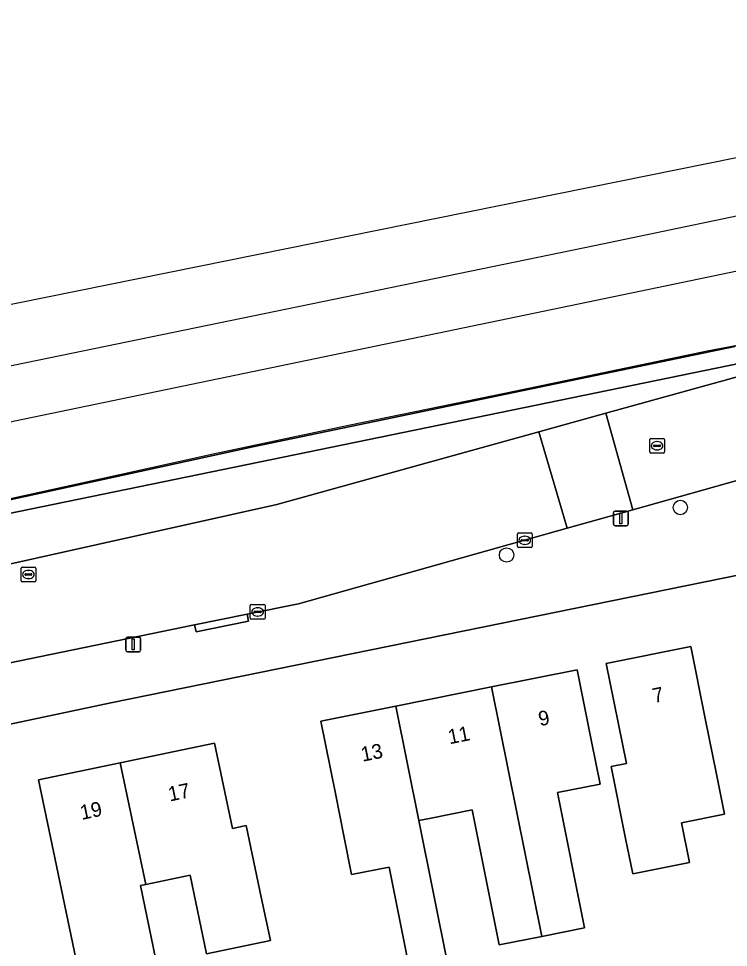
# Model space of a CAD drawing. Extents: x 162989 to 165008, y 383432 to 384338.
# Drawn here: x 164175.4 to 164223.8, y 384168.5 to 384231.8 of the extents above; entities that cross this region are included whole.
import ezdxf

# ---------------------------------------------------------------- set-up
doc = ezdxf.new("R2010")
doc.units = 0
for name, color, linetype in [('IMGEO_Boom', 7, 'Continuous'), ('IMGEO_Erf', 7, 'Continuous'), ('IMGEO_Geluidsscherm', 7, 'Continuous'), ('IMGEO_Groenvoorziening', 7, 'Continuous'), ('IMGEO_Haag', 7, 'Continuous'), ('IMGEO_Kolk', 7, 'Continuous'), ('IMGEO_Lichtmast', 7, 'Continuous'), ('IMGEO_Pand', 7, 'Continuous'), ('IMGEO_Pand_nummerreeks', 7, 'Continuous'), ('IMGEO_Rijbaan_lokaal_gesloten', 7, 'Continuous'), ('IMGEO_Rijbaan_lokaal_open', 7, 'Continuous'), ('IMGEO_Rioolput', 7, 'Continuous'), ('IMGEO_Spoor', 7, 'Continuous'), ('IMGEO_Spoorbaan_halfverhard', 7, 'Continuous'), ('IMGEO_Voetpad_open', 7, 'Continuous')]:
    doc.layers.add(name, color=color, linetype=linetype)

msp = doc.modelspace()

# ---------------------------------------------------------------- linework, layer by layer
at = {"layer": 'IMGEO_Boom'}
for centre in [(164220.485, 384198.529), (164208.651, 384195.29)]:
    msp.add_circle(centre, 0.489, dxfattribs=at)
at = {"layer": 'IMGEO_Erf'}
for points in [[(164247.023, 384197.746), (164245.464, 384197.793), (164245.375, 384198.004), (164230.991, 384195.25), (164181.684, 384185.212), (164136.425, 384175.642), (164077.591, 384163.416), (164035.172, 384154.601)], [(164203.02, 384162.177), (164200.646, 384174.026), (164198.091, 384173.514), (164197.585, 384176.041), (164196.985, 384179.036), (164195.995, 384183.977), (164201.106, 384185.001), (164207.622, 384186.306), (164213.46, 384187.476), (164214.443, 384182.574), (164215.022, 384179.683), (164212.112, 384179.1), (164213.959, 384169.885), (164211.04, 384169.3), (164208.139, 384168.719), (164206.296, 384177.918), (164203.395, 384177.336), (164202.674, 384177.191), (164206.648, 384157.404)]]:
    msp.add_lwpolyline(points, dxfattribs=at)
for points in [[(164215.445, 384187.894), (164221.202, 384189.047), (164222.185, 384184.145), (164222.943, 384180.361), (164223.49, 384177.628), (164220.574, 384177.044), (164221.115, 384174.346), (164217.241, 384173.57), (164216.759, 384175.974), (164215.777, 384180.876), (164216.81, 384181.083)], [(164177.779, 384175.085), (164176.758, 384179.971), (164182.328, 384181.135), (164188.753, 384182.478), (164189.969, 384176.66), (164190.919, 384176.858), (164191.942, 384171.964), (164192.557, 384169.024), (164188.208, 384168.115), (164187.089, 384173.468), (164184.065, 384172.836), (164183.705, 384172.761), (164185.174, 384165.726), (164182.634, 384165.195), (164179.963, 384164.637)]]:
    msp.add_lwpolyline(points, close=True, dxfattribs=at)
at = {"layer": 'IMGEO_Geluidsscherm'}
msp.add_lwpolyline([(164171.413, 384198.388), (164182.191, 384200.754), (164188.653, 384202.187), (164197.889, 384204.143), (164208.612, 384206.353), (164222.309, 384209.203), (164232.177, 384211.07), (164237.019, 384211.987)], dxfattribs=at)
at = {"layer": 'IMGEO_Groenvoorziening'}
for points in [[(163892.745, 384139.603), (163976.433, 384156.982), (164073.867, 384177.406), (164173.737, 384197.907), (164238.498, 384211.23), (164245.279, 384212.748), (164245.015, 384213.611), (164238.302, 384212.109), (164224.204, 384209.495), (164191.357, 384202.662), (164184.194, 384201.103), (164173.545, 384198.786), (164138.86, 384191.809), (164106.067, 384184.851), (164073.689, 384178.288), (164040.716, 384171.257), (164027.429, 384168.427), (164008.211, 384164.605), (163976.248, 384157.863), (163965.539, 384155.519), (163953.785, 384153.248), (163943.293, 384151.084)], [(164013.045, 384161.087), (164068.214, 384172.427), (164075.211, 384173.907), (164100.528, 384179.263), (164113.878, 384181.981), (164118.515, 384182.925), (164132.64, 384185.801), (164174.669, 384194.637), (164193.008, 384198.736), (164210.847, 384203.689), (164215.404, 384204.954), (164225.51, 384207.76), (164243.827, 384211.591), (164248.158, 384212.497), (164247.376, 384214.139), (164245.015, 384213.611), (164245.279, 384212.748), (164238.498, 384211.23), (164173.737, 384197.907), (164073.867, 384177.406), (163976.433, 384156.982)]]:
    msp.add_lwpolyline(points, dxfattribs=at)
at = {"layer": 'IMGEO_Haag'}
msp.add_lwpolyline([(163892.745, 384139.603), (163976.433, 384156.982), (164073.867, 384177.406), (164173.737, 384197.907), (164238.498, 384211.23), (164245.279, 384212.748), (164245.015, 384213.611), (164238.302, 384212.109), (164224.204, 384209.495), (164191.357, 384202.662), (164184.194, 384201.103), (164173.545, 384198.786), (164138.86, 384191.809), (164106.067, 384184.851), (164073.689, 384178.288), (164040.716, 384171.257), (164027.429, 384168.427), (164008.211, 384164.605), (163976.248, 384157.863), (163965.539, 384155.519), (163953.785, 384153.248), (163943.293, 384151.084)], dxfattribs=at)
at = {"layer": 'IMGEO_Kolk'}
for p, q in [((164209.388, 384195.868), (164209.388, 384196.72)), ((164209.463, 384196.794), (164210.315, 384196.794)), ((164209.876, 384196.574), (164209.901, 384196.574)), ((164210.389, 384196.72), (164210.389, 384195.868)), ((164209.647, 384196.288), (164209.647, 384196.3)), ((164210.085, 384196.251), (164209.687, 384196.251)), ((164209.69, 384196.337), (164210.088, 384196.337)), ((164209.899, 384196.014), (164209.874, 384196.014)), ((164210.131, 384196.3), (164210.131, 384196.288)), ((164210.315, 384195.794), (164209.463, 384195.794)), ((164191.192, 384190.988), (164191.192, 384191.84)), ((164191.267, 384191.914), (164192.119, 384191.914)), ((164191.451, 384191.408), (164191.451, 384191.42)), ((164191.494, 384191.457), (164191.892, 384191.457)), ((164191.68, 384191.694), (164191.705, 384191.694)), ((164191.935, 384191.42), (164191.935, 384191.408)), ((164192.193, 384191.84), (164192.193, 384190.988)), ((164192.119, 384190.914), (164191.267, 384190.914)), ((164191.889, 384191.371), (164191.491, 384191.371)), ((164191.703, 384191.134), (164191.678, 384191.134))]:
    msp.add_line(p, q, dxfattribs=at)
for points in [[(164209.388, 384195.868), (164209.388, 384196.72)], [(164209.463, 384196.794), (164210.315, 384196.794)], [(164210.389, 384196.72), (164210.389, 384195.868)], [(164210.315, 384195.794), (164209.463, 384195.794)], [(164191.192, 384190.988), (164191.192, 384191.84)], [(164191.267, 384191.914), (164192.119, 384191.914)], [(164192.193, 384191.84), (164192.193, 384190.988)], [(164192.119, 384190.914), (164191.267, 384190.914)]]:
    msp.add_lwpolyline(points, dxfattribs=at)
for centre, radius, start, end in [((164209.465, 384196.718), 0.0765, 91.55205, 178.44795), ((164209.465, 384196.718), 0.0765, 91.55205, 178.44795), ((164210.313, 384196.718), 0.0765, 1.55205, 88.44795), ((164210.313, 384196.718), 0.0765, 1.55205, 88.44795), ((164209.465, 384195.87), 0.0765, 181.55205, 268.44795), ((164209.465, 384195.87), 0.0765, 181.55205, 268.44795), ((164209.687, 384196.297), 0.0403, 85.87752, 175.75265), ((164209.684, 384196.287), 0.0366, 178.93798, 274.71019), ((164210.088, 384196.294), 0.043, 264.86636, 352.45326), ((164210.092, 384196.299), 0.0386, 1.73085, 96.63898), ((164210.313, 384195.87), 0.0765, 271.55205, 358.44795), ((164210.313, 384195.87), 0.0765, 271.55205, 358.44795), ((164191.269, 384191.838), 0.0765, 91.55205, 178.44795), ((164191.269, 384191.838), 0.0765, 91.55205, 178.44795), ((164191.491, 384191.417), 0.0403, 85.87752, 175.75265), ((164191.488, 384191.407), 0.0366, 178.93798, 274.71019), ((164191.892, 384191.414), 0.043, 264.86636, 352.45326), ((164191.896, 384191.419), 0.0386, 1.73085, 96.63898), ((164192.117, 384191.838), 0.0765, 1.55205, 88.44795), ((164192.117, 384191.838), 0.0765, 1.55205, 88.44795), ((164191.269, 384190.99), 0.0765, 181.55205, 268.44795), ((164191.269, 384190.99), 0.0765, 181.55205, 268.44795), ((164192.117, 384190.99), 0.0765, 271.55205, 358.44795), ((164192.117, 384190.99), 0.0765, 271.55205, 358.44795)]:
    msp.add_arc(centre, radius, start, end, dxfattribs=at)
for centre, major_axis, ratio, start_param, end_param in [((164209.875, 384196.294), (-0.387, 0.002), 0.722429, 4.712389, 7.853982), ((164209.9, 384196.294), (-0.39, 0.002), 0.717154, 1.570796, 4.712389), ((164191.679, 384191.414), (-0.387, 0.002), 0.722429, 4.712389, 7.853982), ((164191.704, 384191.414), (-0.39, 0.002), 0.717154, 1.570796, 4.712389)]:
    msp.add_ellipse(centre, major_axis=major_axis, ratio=ratio, start_param=start_param, end_param=end_param, dxfattribs=at)
at = {"layer": 'IMGEO_Lichtmast'}
for p, q in [((164215.938, 384197.387), (164215.938, 384198.187)), ((164215.938, 384198.187), (164215.938, 384197.387)), ((164216.038, 384198.287), (164216.828, 384198.287)), ((164216.828, 384198.287), (164216.038, 384198.287)), ((164216.928, 384198.187), (164216.928, 384197.387)), ((164216.928, 384197.387), (164216.928, 384198.187)), ((164216.828, 384197.287), (164216.038, 384197.287)), ((164216.038, 384197.287), (164216.828, 384197.287)), ((164182.72, 384188.798), (164182.72, 384189.598)), ((164182.72, 384189.598), (164182.72, 384188.798)), ((164182.82, 384189.698), (164183.61, 384189.698)), ((164183.61, 384189.698), (164182.82, 384189.698)), ((164183.71, 384189.598), (164183.71, 384188.798)), ((164183.71, 384188.798), (164183.71, 384189.598)), ((164183.61, 384188.698), (164182.82, 384188.698)), ((164182.82, 384188.698), (164183.61, 384188.698))]:
    msp.add_line(p, q, dxfattribs=at)
for points in [[(164216.358, 384198.162), (164216.508, 384198.162), (164216.508, 384197.412), (164216.358, 384197.412), (164216.358, 384198.162)], [(164183.14, 384189.573), (164183.29, 384189.573), (164183.29, 384188.823), (164183.14, 384188.823), (164183.14, 384189.573)]]:
    msp.add_lwpolyline(points, dxfattribs=at)
for centre, start, end in [((164216.038, 384198.187), 90, 180), ((164216.038, 384198.187), 90, 180), ((164216.828, 384198.187), 0, 90), ((164216.828, 384198.187), 360, 90), ((164216.038, 384197.387), 180, 270), ((164216.038, 384197.387), 180, 270), ((164216.828, 384197.387), 270, 0), ((164216.828, 384197.387), 270, 0), ((164182.82, 384189.598), 90, 180), ((164182.82, 384189.598), 90, 180), ((164183.61, 384189.598), 0, 90), ((164183.61, 384189.598), 360, 90), ((164182.82, 384188.798), 180, 270), ((164182.82, 384188.798), 180, 270), ((164183.61, 384188.798), 270, 0), ((164183.61, 384188.798), 270, 0)]:
    msp.add_arc(centre, 0.1, start, end, dxfattribs=at)
at = {"layer": 'IMGEO_Pand'}
for points in [[(164222.185, 384184.145), (164221.202, 384189.047), (164215.445, 384187.894), (164216.81, 384181.083), (164215.777, 384180.876), (164216.759, 384175.974), (164217.241, 384173.57), (164221.115, 384174.346), (164220.574, 384177.044), (164223.49, 384177.628), (164222.943, 384180.361)], [(164207.622, 384186.306), (164211.04, 384169.3), (164213.959, 384169.885), (164212.112, 384179.1), (164215.022, 384179.683), (164214.443, 384182.574), (164213.46, 384187.476)], [(164207.622, 384186.306), (164201.106, 384185.001), (164202.674, 384177.191), (164203.395, 384177.336), (164206.296, 384177.918), (164208.139, 384168.719), (164211.04, 384169.3)], [(164201.106, 384185.001), (164195.995, 384183.977), (164196.985, 384179.036), (164197.585, 384176.041), (164198.091, 384173.514), (164200.646, 384174.026), (164203.02, 384162.177), (164202.452, 384162.075), (164203.429, 384156.8), (164203.437, 384156.759), (164206.648, 384157.404), (164202.674, 384177.191)], [(164184.065, 384172.836), (164187.089, 384173.468), (164188.208, 384168.115), (164192.557, 384169.024), (164191.942, 384171.964), (164190.919, 384176.858), (164189.969, 384176.66), (164188.753, 384182.478), (164182.328, 384181.135)], [(164184.065, 384172.836), (164182.328, 384181.135), (164176.758, 384179.971), (164177.779, 384175.085), (164179.963, 384164.637), (164182.634, 384165.195), (164185.174, 384165.726), (164183.705, 384172.761)]]:
    msp.add_lwpolyline(points, close=True, dxfattribs=at)
at = {"layer": 'IMGEO_Rijbaan_lokaal_gesloten'}
msp.add_lwpolyline([(164248.757, 384212.622), (164248.158, 384212.497), (164243.827, 384211.591), (164225.51, 384207.76), (164215.404, 384204.954), (164217.248, 384198.372), (164226.93, 384201.094), (164244.619, 384204.64), (164249.169, 384205.552), (164261.438, 384207.238)], dxfattribs=at)
msp.add_lwpolyline([(164151.108, 384182.957), (164157.853, 384184.381), (164170.754, 384187.105), (164173.805, 384187.749), (164187.396, 384190.533), (164190.968, 384191.257), (164194.467, 384191.967), (164212.777, 384197.115), (164210.847, 384203.689), (164193.008, 384198.736), (164174.669, 384194.637), (164132.64, 384185.801), (164118.515, 384182.925), (164119.87, 384176.388), (164129.874, 384178.473), (164133.253, 384179.185), (164134.588, 384179.467), (164137.721, 384180.13)], close=True, dxfattribs=at)
at = {"layer": 'IMGEO_Rijbaan_lokaal_open'}
msp.add_lwpolyline([(164210.847, 384203.689), (164212.777, 384197.115), (164217.248, 384198.372), (164215.404, 384204.954)], close=True, dxfattribs=at)
at = {"layer": 'IMGEO_Rioolput'}
for p, q in [((164218.403, 384202.312), (164218.403, 384203.164)), ((164218.478, 384203.238), (164219.33, 384203.238)), ((164218.891, 384203.018), (164218.916, 384203.018)), ((164219.404, 384203.164), (164219.404, 384202.312)), ((164219.33, 384202.238), (164218.478, 384202.238)), ((164218.662, 384202.732), (164218.662, 384202.744)), ((164219.1, 384202.695), (164218.702, 384202.695)), ((164218.705, 384202.781), (164219.103, 384202.781)), ((164218.914, 384202.458), (164218.889, 384202.458)), ((164219.146, 384202.744), (164219.146, 384202.732)), ((164175.573, 384193.541), (164175.573, 384194.393)), ((164175.648, 384194.467), (164176.5, 384194.467)), ((164175.832, 384193.961), (164175.832, 384193.973)), ((164175.875, 384194.01), (164176.273, 384194.01)), ((164176.061, 384194.247), (164176.086, 384194.247)), ((164176.316, 384193.973), (164176.316, 384193.961)), ((164176.574, 384194.393), (164176.574, 384193.541)), ((164176.5, 384193.467), (164175.648, 384193.467)), ((164176.27, 384193.924), (164175.872, 384193.924)), ((164176.084, 384193.687), (164176.059, 384193.687))]:
    msp.add_line(p, q, dxfattribs=at)
for points in [[(164218.403, 384202.312), (164218.403, 384203.164)], [(164218.478, 384203.238), (164219.33, 384203.238)], [(164219.404, 384203.164), (164219.404, 384202.312)], [(164219.33, 384202.238), (164218.478, 384202.238)], [(164175.573, 384193.541), (164175.573, 384194.393)], [(164175.648, 384194.467), (164176.5, 384194.467)], [(164176.574, 384194.393), (164176.574, 384193.541)], [(164176.5, 384193.467), (164175.648, 384193.467)]]:
    msp.add_lwpolyline(points, dxfattribs=at)
for centre, radius, start, end in [((164218.48, 384203.162), 0.0765, 91.55205, 178.44795), ((164218.48, 384203.162), 0.0765, 91.55205, 178.44795), ((164219.328, 384203.162), 0.0765, 1.55205, 88.44795), ((164219.328, 384203.162), 0.0765, 1.55205, 88.44795), ((164218.48, 384202.314), 0.0765, 181.55205, 268.44795), ((164218.48, 384202.314), 0.0765, 181.55205, 268.44795), ((164218.702, 384202.741), 0.0403, 85.87752, 175.75265), ((164218.699, 384202.731), 0.0366, 178.93798, 274.71019), ((164219.103, 384202.738), 0.043, 264.86636, 352.45326), ((164219.107, 384202.743), 0.0386, 1.73085, 96.63898), ((164219.328, 384202.314), 0.0765, 271.55205, 358.44795), ((164219.328, 384202.314), 0.0765, 271.55205, 358.44795), ((164175.65, 384194.391), 0.0765, 91.55205, 178.44795), ((164175.65, 384194.391), 0.0765, 91.55205, 178.44795), ((164175.872, 384193.97), 0.0403, 85.87752, 175.75265), ((164175.869, 384193.96), 0.0366, 178.93798, 274.71019), ((164176.273, 384193.967), 0.043, 264.86636, 352.45326), ((164176.277, 384193.972), 0.0386, 1.73085, 96.63898), ((164176.498, 384194.391), 0.0765, 1.55205, 88.44795), ((164176.498, 384194.391), 0.0765, 1.55205, 88.44795), ((164175.65, 384193.543), 0.0765, 181.55205, 268.44795), ((164175.65, 384193.543), 0.0765, 181.55205, 268.44795), ((164176.498, 384193.543), 0.0765, 271.55205, 358.44795), ((164176.498, 384193.543), 0.0765, 271.55205, 358.44795)]:
    msp.add_arc(centre, radius, start, end, dxfattribs=at)
for centre, major_axis, ratio, start_param, end_param in [((164218.89, 384202.738), (-0.387, 0.002), 0.722429, 4.712389, 7.853982), ((164218.915, 384202.738), (-0.39, 0.002), 0.717154, 1.570796, 4.712389), ((164176.06, 384193.967), (-0.387, 0.002), 0.722429, 4.712389, 7.853982), ((164176.085, 384193.967), (-0.39, 0.002), 0.717154, 1.570796, 4.712389)]:
    msp.add_ellipse(centre, major_axis=major_axis, ratio=ratio, start_param=start_param, end_param=end_param, dxfattribs=at)
at = {"layer": 'IMGEO_Spoor'}
for points in [[(164788.231, 384335.773), (164684.182, 384314.23), (164649.743, 384306.978), (164549.034, 384286.117), (164446.504, 384264.637), (164353.435, 384245.24), (164284.243, 384230.902), (164214.646, 384216.358), (164173.585, 384207.909), (164102.605, 384193.066), (164031.754, 384178.409), (163810.752, 384132.353), (163673.071, 384103.86), (163574.904, 384083.455)], [(164789.572, 384332.389), (164775.58, 384329.429), (164644.744, 384302.256), (164570.629, 384286.722), (164345.336, 384239.894), (164220.116, 384213.747), (164092.662, 384187.275), (164071.527, 384182.957), (163942.979, 384156.119), (163900.983, 384147.477), (163806.025, 384127.659), (163575.669, 384079.775)]]:
    msp.add_lwpolyline(points, dxfattribs=at)
at = {"layer": 'IMGEO_Spoorbaan_halfverhard'}
for points in [[(164232.616, 384224.049), (164160.958, 384209.557)], [(164173.545, 384198.786), (164184.194, 384201.103), (164191.357, 384202.662), (164224.204, 384209.495)]]:
    msp.add_lwpolyline(points, dxfattribs=at)
at = {"layer": 'IMGEO_Voetpad_open'}
for points in [[(164249.169, 384205.552), (164244.619, 384204.64), (164226.93, 384201.094), (164217.248, 384198.372), (164212.777, 384197.115), (164194.467, 384191.967), (164190.968, 384191.257), (164191.064, 384190.78), (164187.492, 384190.052), (164187.396, 384190.533), (164173.805, 384187.749)], [(164181.684, 384185.212), (164230.991, 384195.25), (164245.375, 384198.004), (164256.485, 384200.076)], [(164033.121, 384155.733), (164035.172, 384154.601), (164077.591, 384163.416), (164136.425, 384175.642), (164181.684, 384185.212)]]:
    msp.add_lwpolyline(points, dxfattribs=at)
msp.add_lwpolyline([(164190.968, 384191.257), (164187.396, 384190.533), (164187.492, 384190.052), (164191.064, 384190.78)], close=True, dxfattribs=at)

# ---------------------------------------------------------------- texts
at = {"layer": 'IMGEO_Pand_nummerreeks'}
for s, rotation, p in [('7', 11.32738, (164218.697, 384185.2)), ('9', 11.32886, (164210.924, 384183.622)), ('11', 11.32738, (164204.763, 384182.388)), ('13', 11.32738, (164198.83, 384181.2)), ('17', 11.8051, (164185.706, 384178.49)), ('19', 11.80293, (164179.709, 384177.236))]:
    msp.add_text(s, height=1, rotation=rotation, dxfattribs=at).set_placement(p)

doc.saveas('drawing.dxf')
